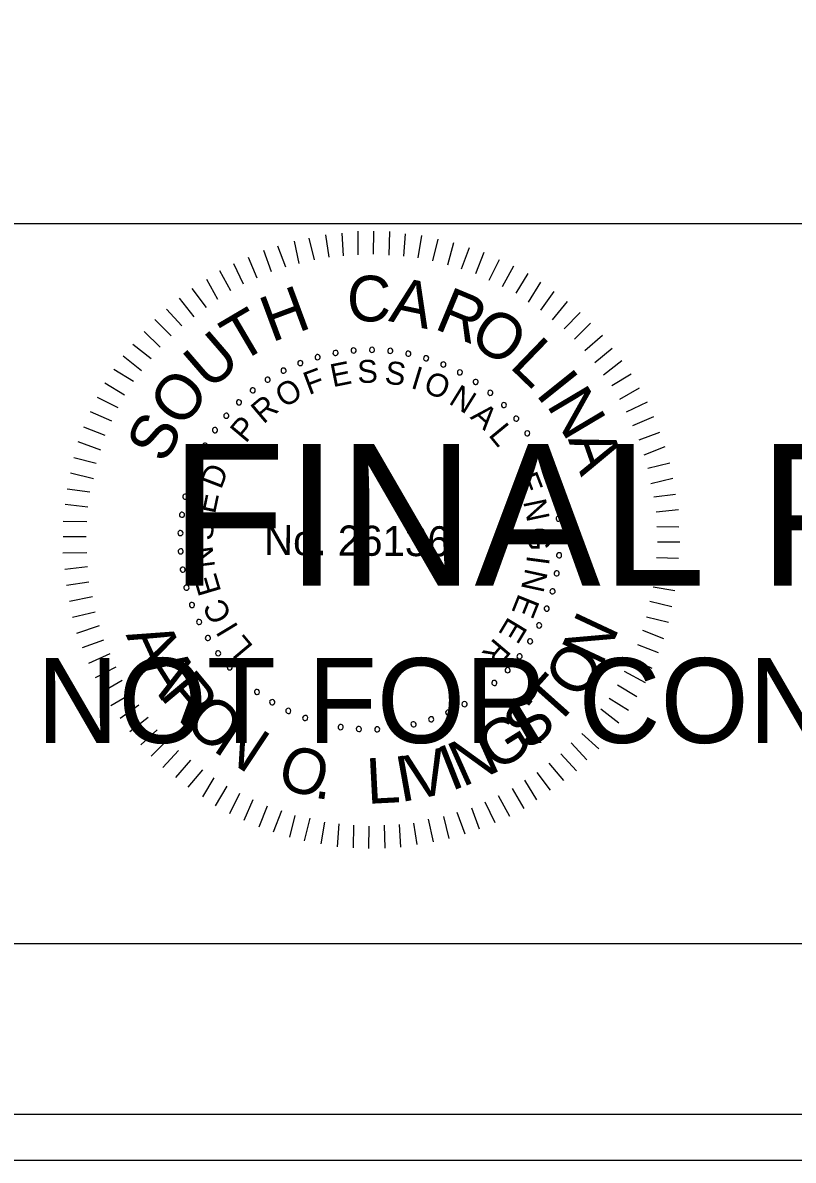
# Model space of a CAD drawing. Extents: x 967 to 1623, y 964 to 7064.
# Drawn here: x 1170.56 to 1189.3, y 2643.72 to 2671.36 of the extents above; entities that cross this region are included whole.
import ezdxf

# ---------------------------------------------------------------- set-up
doc = ezdxf.new("R2010")
doc.units = 0
for name, color, linetype in [('RD_SHT_Bndy', 7, 'Continuous'), ('RD_SHT_IplotShp', 7, 'Continuous'), ('RD_SHT_Misc1', 7, 'Continuous'), ('RD_SHT_Misc2', 7, 'Continuous'), ('RD_Sketch1', 7, 'Continuous')]:
    doc.layers.add(name, color=color, linetype=linetype)

msp = doc.modelspace()

# ---------------------------------------------------------------- linework, layer by layer
at = {"layer": 'RD_SHT_Bndy'}
for p, q in [((996.114, 2666.486), (1323.886, 2666.486)), ((1323.886, 2648.983), (996.114, 2648.983))]:
    msp.add_line(p, q, dxfattribs=at)
at = {"layer": 'RD_SHT_IplotShp'}
for points in [[(967.409, 2643.72), (1326.285, 2643.72), (1326.285, 2863.72), (967.409, 2863.72)], [(988.525, 2644.84), (1326.285, 2644.84), (1326.285, 2862.6), (988.525, 2862.6)]]:
    msp.add_lwpolyline(points, close=True, dxfattribs=at)
at = {"layer": 'RD_SHT_Misc1'}
for p, q in [((1178.01, 2665.663), (1177.93, 2666.209)), ((1178.364, 2665.699), (1178.33, 2666.244)), ((1178.717, 2665.719), (1178.722, 2666.295)), ((1179.093, 2665.739), (1179.098, 2666.292)), ((1179.469, 2665.713), (1179.489, 2666.288)), ((1179.829, 2665.687), (1179.872, 2666.231)), ((1180.174, 2665.646), (1180.271, 2666.19)), ((1176.964, 2665.419), (1176.769, 2665.935)), ((1177.287, 2665.508), (1177.169, 2666.054)), ((1177.657, 2665.597), (1177.53, 2666.128)), ((1180.535, 2665.573), (1180.662, 2666.102)), ((1180.902, 2665.478), (1181.045, 2666.022)), ((1181.231, 2665.384), (1181.428, 2665.896)), ((1176.264, 2665.156), (1176.053, 2665.657)), ((1176.61, 2665.306), (1176.423, 2665.83)), ((1181.584, 2665.265), (1181.78, 2665.786)), ((1181.905, 2665.109), (1182.154, 2665.606)), ((1175.624, 2664.846), (1175.352, 2665.332)), ((1175.933, 2665.005), (1175.699, 2665.506)), ((1182.226, 2664.953), (1182.506, 2665.45)), ((1175.308, 2664.634), (1175.036, 2665.12)), ((1182.562, 2664.789), (1182.85, 2665.27)), ((1182.86, 2664.572), (1183.163, 2665.053)), ((1175.03, 2664.445), (1174.681, 2664.9)), ((1183.158, 2664.378), (1183.484, 2664.828)), ((1174.729, 2664.217), (1174.372, 2664.665)), ((1183.447, 2664.145), (1183.811, 2664.587)), ((1174.435, 2663.997), (1174.062, 2664.399)), ((1183.729, 2663.92), (1184.116, 2664.316)), ((1174.172, 2663.753), (1173.776, 2664.148)), ((1183.98, 2663.672), (1184.368, 2664.061)), ((1173.909, 2663.479), (1173.52, 2663.858)), ((1184.232, 2663.394), (1184.657, 2663.767)), ((1173.684, 2663.197), (1173.242, 2663.546)), ((1184.475, 2663.108), (1184.892, 2663.45)), ((1173.451, 2662.9), (1173.009, 2663.256)), ((1184.687, 2662.807), (1185.128, 2663.156)), ((1173.257, 2662.64), (1172.776, 2662.936)), ((1184.885, 2662.544), (1185.355, 2662.832)), ((1173.039, 2662.312), (1172.559, 2662.6)), ((1185.081, 2662.213), (1185.56, 2662.493)), ((1172.883, 2662.006), (1172.379, 2662.256)), ((1185.24, 2661.904), (1185.756, 2662.145)), ((1172.727, 2661.677), (1172.215, 2661.904)), ((1185.399, 2661.573), (1185.907, 2661.791)), ((1172.571, 2661.333), (1172.051, 2661.53)), ((1172.461, 2660.974), (1171.91, 2661.178)), ((1185.549, 2661.226), (1186.057, 2661.414)), ((1185.669, 2660.865), (1186.185, 2661.06)), ((1172.351, 2660.652), (1171.807, 2660.787)), ((1185.759, 2660.541), (1186.297, 2660.667)), ((1172.286, 2660.276), (1171.727, 2660.419)), ((1185.832, 2660.165), (1186.371, 2660.298)), ((1172.191, 2659.955), (1171.647, 2660.029)), ((1185.906, 2659.842), (1186.436, 2659.906)), ((1172.15, 2659.587), (1171.598, 2659.653)), ((1185.964, 2659.473), (1186.51, 2659.53)), ((1172.124, 2659.234), (1171.548, 2659.239)), ((1185.977, 2659.12), (1186.514, 2659.115)), ((1172.105, 2658.866), (1171.545, 2658.871)), ((1185.997, 2658.751), (1186.542, 2658.747)), ((1172.118, 2658.482), (1171.542, 2658.471)), ((1172.138, 2658.136), (1171.585, 2658.072)), ((1185.971, 2658.368), (1186.508, 2658.348)), ((1185.952, 2658.022), (1186.497, 2657.949)), ((1172.173, 2657.768), (1171.627, 2657.688)), ((1185.888, 2657.655), (1186.417, 2657.566)), ((1172.262, 2657.414), (1171.701, 2657.296)), ((1185.808, 2657.302), (1186.345, 2657.175)), ((1172.321, 2657.037), (1171.774, 2656.911)), ((1185.729, 2656.926), (1186.265, 2656.792)), ((1172.425, 2656.707), (1171.871, 2656.519)), ((1185.634, 2656.597), (1186.146, 2656.401)), ((1172.53, 2656.36), (1172.007, 2656.173)), ((1185.508, 2656.253), (1186.013, 2656.057)), ((1172.681, 2656.029), (1172.165, 2655.788)), ((1185.352, 2655.924), (1185.857, 2655.675)), ((1172.831, 2655.705), (1172.323, 2655.441)), ((1172.982, 2655.374), (1172.497, 2655.094)), ((1185.188, 2655.603), (1185.7, 2655.33)), ((1185.024, 2655.274), (1185.498, 2654.987)), ((1173.194, 2655.042), (1172.709, 2654.762)), ((1184.822, 2654.946), (1185.288, 2654.658)), ((1173.384, 2654.78), (1172.936, 2654.453)), ((1184.62, 2654.687), (1185.055, 2654.353)), ((1173.612, 2654.478), (1173.164, 2654.129)), ((1184.403, 2654.389), (1184.814, 2654.033)), ((1173.832, 2654.177), (1173.437, 2653.812)), ((1184.155, 2654.092), (1184.574, 2653.72)), ((1174.091, 2653.945), (1173.689, 2653.541)), ((1183.899, 2653.864), (1184.28, 2653.454)), ((1174.35, 2653.674), (1173.97, 2653.263)), ((1174.64, 2653.442), (1174.275, 2653.022)), ((1183.644, 2653.597), (1184.024, 2653.18)), ((1174.937, 2653.209), (1174.58, 2652.782)), ((1183.065, 2653.141), (1183.384, 2652.709)), ((1183.358, 2653.37), (1183.715, 2652.944)), ((1175.212, 2653.014), (1174.932, 2652.549)), ((1182.764, 2652.952), (1183.059, 2652.482)), ((1175.525, 2652.812), (1175.245, 2652.331)), ((1175.83, 2652.633), (1175.588, 2652.136)), ((1182.463, 2652.755), (1182.743, 2652.269)), ((1176.159, 2652.477), (1175.94, 2651.98)), ((1176.503, 2652.321), (1176.307, 2651.816)), ((1181.8, 2652.431), (1182.041, 2651.93)), ((1182.124, 2652.581), (1182.396, 2652.08)), ((1176.855, 2652.211), (1176.651, 2651.69)), ((1177.177, 2652.1), (1177.05, 2651.572)), ((1177.545, 2652.036), (1177.409, 2651.484)), ((1180.791, 2652.07), (1180.926, 2651.54)), ((1181.122, 2652.175), (1181.31, 2651.652)), ((1181.476, 2652.28), (1181.664, 2651.771)), ((1177.897, 2651.933), (1177.808, 2651.412)), ((1178.25, 2651.892), (1178.207, 2651.34)), ((1178.603, 2651.866), (1178.598, 2651.313)), ((1178.978, 2651.84), (1178.974, 2651.295)), ((1179.355, 2651.86), (1179.365, 2651.307)), ((1179.715, 2651.88), (1179.749, 2651.327)), ((1180.061, 2651.915), (1180.149, 2651.393)), ((1180.423, 2652.012), (1180.541, 2651.458))]:
    msp.add_line(p, q, dxfattribs=at)
for centre, start, end in [((1178.168, 2663.337), 10.6038, 190.6038), ((1178.609, 2663.397), 5.0653, 185.0653), ((1178.609, 2663.397), 185.0653, 5.0653), ((1179.055, 2663.414), 359.5268, 179.5268), ((1179.055, 2663.414), 179.5268, 359.5268), ((1179.5, 2663.388), 353.9884, 173.9884), ((1179.5, 2663.388), 173.9884, 353.9884), ((1179.94, 2663.319), 348.4499, 168.4499), ((1177.312, 2663.091), 21.6807, 201.6807), ((1177.312, 2663.091), 201.6807, 21.6807), ((1177.734, 2663.235), 16.1422, 196.1422), ((1177.734, 2663.235), 196.1422, 16.1422), ((1178.168, 2663.337), 190.6038, 10.6038), ((1179.94, 2663.319), 168.4499, 348.4499), ((1180.372, 2663.208), 162.9114, 342.9114), ((1180.372, 2663.208), 342.9114, 162.9114), ((1180.79, 2663.056), 337.373, 157.373), ((1176.906, 2662.908), 27.2191, 207.2191), ((1176.906, 2662.908), 207.2191, 27.2191), ((1180.79, 2663.056), 157.373, 337.373), ((1181.193, 2662.864), 151.8345, 331.8345), ((1181.193, 2662.864), 331.8345, 151.8345), ((1176.52, 2662.686), 32.7576, 212.7576), ((1176.52, 2662.686), 212.7576, 32.7576), ((1181.574, 2662.634), 146.2961, 326.2961), ((1181.574, 2662.634), 326.2961, 146.2961), ((1176.156, 2662.428), 38.2961, 218.2961), ((1176.156, 2662.428), 218.2961, 38.2961), ((1181.932, 2662.368), 140.7576, 320.7576), ((1181.932, 2662.368), 320.7576, 140.7576), ((1175.82, 2662.135), 43.8345, 223.8345), ((1175.82, 2662.135), 223.8345, 43.8345), ((1182.263, 2662.069), 135.2191, 315.2191), ((1182.263, 2662.069), 315.2191, 135.2191), ((1175.513, 2661.812), 49.373, 229.373), ((1175.513, 2661.812), 229.373, 49.373), ((1182.563, 2661.74), 129.6807, 309.6807), ((1182.563, 2661.74), 309.6807, 129.6807), ((1175.239, 2661.461), 54.9114, 234.9114), ((1175.239, 2661.461), 234.9114, 54.9114), ((1182.83, 2661.383), 124.1422, 304.1422), ((1182.83, 2661.383), 304.1422, 124.1422), ((1175, 2661.085), 60.4499, 240.4499), ((1175, 2661.085), 240.4499, 60.4499), ((1183.061, 2661.002), 118.6038, 298.6038), ((1183.061, 2661.002), 298.6038, 118.6038), ((1174.798, 2660.687), 65.9884, 245.9884), ((1174.798, 2660.687), 245.9884, 65.9884), ((1183.255, 2660.601), 113.0653, 293.0653), ((1183.255, 2660.601), 293.0653, 113.0653), ((1174.636, 2660.272), 71.5268, 251.5268), ((1174.636, 2660.272), 251.5268, 71.5268), ((1183.408, 2660.182), 107.5268, 287.5268), ((1183.408, 2660.182), 287.5268, 107.5268), ((1174.514, 2659.843), 77.0653, 257.0653), ((1174.514, 2659.843), 257.0653, 77.0653), ((1183.521, 2659.751), 101.9884, 281.9884), ((1183.521, 2659.751), 281.9884, 101.9884), ((1174.435, 2659.405), 82.6038, 262.6038), ((1174.435, 2659.405), 262.6038, 82.6038), ((1183.592, 2659.311), 96.4499, 276.4499), ((1183.592, 2659.311), 276.4499, 96.4499), ((1174.398, 2658.961), 88.1422, 268.1422), ((1174.398, 2658.961), 268.1422, 88.1422), ((1183.619, 2658.866), 90.9114, 270.9114), ((1183.619, 2658.866), 270.9114, 90.9114), ((1174.404, 2658.515), 93.6807, 273.6807), ((1174.404, 2658.515), 273.6807, 93.6807), ((1183.604, 2658.421), 85.373, 265.373), ((1183.604, 2658.421), 265.373, 85.373), ((1174.453, 2658.072), 99.2191, 279.2191), ((1174.453, 2658.072), 279.2191, 99.2191), ((1183.546, 2657.979), 79.8345, 259.8345), ((1183.546, 2657.979), 259.8345, 79.8345), ((1174.545, 2657.636), 104.7576, 284.7576), ((1174.545, 2657.636), 284.7576, 104.7576), ((1183.445, 2657.545), 74.2961, 254.2961), ((1183.445, 2657.545), 254.2961, 74.2961), ((1174.678, 2657.211), 110.2961, 290.2961), ((1174.678, 2657.211), 290.2961, 110.2961), ((1183.303, 2657.122), 68.7576, 248.7576), ((1183.303, 2657.122), 248.7576, 68.7576), ((1174.852, 2656.8), 115.8345, 295.8345), ((1174.852, 2656.8), 295.8345, 115.8345), ((1183.121, 2656.716), 63.2191, 243.2191), ((1183.121, 2656.716), 243.2191, 63.2191), ((1175.065, 2656.409), 121.373, 301.373), ((1175.065, 2656.409), 301.373, 121.373), ((1182.9, 2656.328), 57.6807, 237.6807), ((1182.9, 2656.328), 237.6807, 57.6807), ((1175.314, 2656.039), 126.9114, 306.9114), ((1175.314, 2656.039), 306.9114, 126.9114), ((1182.643, 2655.964), 52.1422, 232.1422), ((1182.643, 2655.964), 232.1422, 52.1422), ((1175.598, 2655.696), 132.4499, 312.4499), ((1175.598, 2655.696), 312.4499, 132.4499), ((1182.353, 2655.627), 46.6038, 226.6038), ((1182.353, 2655.627), 226.6038, 46.6038), ((1175.914, 2655.381), 137.9884, 317.9884), ((1175.914, 2655.381), 317.9884, 137.9884), ((1182.03, 2655.319), 41.0653, 221.0653), ((1182.03, 2655.319), 221.0653, 41.0653), ((1176.258, 2655.099), 143.5268, 323.5268), ((1176.258, 2655.099), 323.5268, 143.5268), ((1181.68, 2655.043), 35.5268, 215.5268), ((1181.68, 2655.043), 215.5268, 35.5268), ((1176.629, 2654.851), 149.0653, 329.0653), ((1176.629, 2654.851), 329.0653, 149.0653), ((1181.305, 2654.803), 29.9884, 209.9884), ((1181.305, 2654.803), 209.9884, 29.9884), ((1177.021, 2654.639), 154.6038, 334.6038), ((1177.021, 2654.639), 334.6038, 154.6038), ((1177.432, 2654.467), 340.1422, 160.1422), ((1180.908, 2654.6), 24.4499, 204.4499), ((1180.908, 2654.6), 204.4499, 24.4499), ((1177.432, 2654.467), 160.1422, 340.1422), ((1177.858, 2654.335), 165.6807, 345.6807), ((1177.858, 2654.335), 345.6807, 165.6807), ((1178.294, 2654.245), 351.2191, 171.2191), ((1178.294, 2654.245), 171.2191, 351.2191), ((1178.737, 2654.198), 356.7576, 176.7576), ((1179.183, 2654.193), 2.2961, 182.2961), ((1179.627, 2654.232), 7.8345, 187.8345), ((1180.065, 2654.313), 13.373, 193.373), ((1180.065, 2654.313), 193.373, 13.373), ((1180.494, 2654.436), 18.9114, 198.9114), ((1180.494, 2654.436), 198.9114, 18.9114), ((1178.737, 2654.198), 176.7576, 356.7576), ((1179.183, 2654.193), 182.2961, 2.2961), ((1179.627, 2654.232), 187.8345, 7.8345)]:
    msp.add_arc(centre, 0.0627, start, end, dxfattribs=at)
at = {"layer": 'RD_Sketch1'}
msp.add_lwpolyline([(967.409, 2643.72), (1326.285, 2643.72), (1326.285, 2863.72), (967.409, 2863.72)], close=True, dxfattribs=at)

# ---------------------------------------------------------------- texts
at = {"layer": 'RD_SHT_Misc1'}
for s, height, rotation, p in [('C', 1.11, 359.5482, (1178.442, 2664.108)), ('A', 1.11, 348.1981, (1179.439, 2664.115)), ('H', 1.11, 20.3637, (1176.614, 2663.587)), ('R', 1.11, 337.4344, (1180.541, 2663.937)), ('T', 1.11, 30.4992, (1175.828, 2663.072)), ('O', 1.108, 326.5869, (1181.366, 2663.609)), ('U', 1.11, 40.8022, (1175.102, 2662.403)), ('L', 1.11, 315.9488, (1182.373, 2663.003)), ('E', 0.557, 11.4103, (1178.103, 2662.503)), ('S', 0.557, 2.208, (1178.709, 2662.601)), ('S', 0.557, 352.6608, (1179.346, 2662.599)), ('O', 1.11, 52.0267, (1174.435, 2661.474)), ('F', 0.557, 20.6127, (1177.52, 2662.309)), ('I', 0.557, 343.1136, (1179.975, 2662.491)), ('O', 0.557, 338.4392, (1180.274, 2662.401)), ('I', 1.11, 308.6613, (1183.011, 2662.338)), ('O', 0.557, 30.8477, (1176.917, 2661.987)), ('N', 0.557, 328.2042, (1180.896, 2662.12)), ('R', 0.557, 40.3949, (1176.415, 2661.594)), ('N', 1.11, 300.7037, (1183.285, 2662.075)), ('A', 0.557, 318.657, (1181.424, 2661.762)), ('S', 1.108, 63.2511, (1174.029, 2660.619)), ('P', 0.557, 49.9421, (1175.985, 2661.124)), ('L', 0.557, 309.4546, (1181.869, 2661.339)), ('A', 1.11, 289.4792, (1183.814, 2661.243)), ('D', 0.557, 69.0364, (1175.386, 2660.003)), ('E', 0.557, 291.049, (1182.53, 2660.307)), ('E', 0.557, 78.2388, (1175.238, 2659.407)), ('N', 0.557, 281.8466, (1182.728, 2659.726)), ('S', 0.557, 87.786, (1175.187, 2658.772)), ('No. 26136', 0.7311, 359.5268, (1176.429, 2658.43)), ('G', 0.557, 272.2995, (1182.833, 2659.097)), ('N', 0.557, 97.3332, (1175.242, 2658.137)), ('I', 0.557, 262.4084, (1182.83, 2658.437)), ('E', 0.557, 106.5355, (1175.394, 2657.541)), ('N', 0.557, 257.7339, (1182.789, 2658.127)), ('C', 0.557, 116.4266, (1175.661, 2656.938)), ('E', 0.557, 248.1867, (1182.628, 2657.511)), ('N', 1.105, 64.8922, (1184.632, 2655.684)), ('I', 0.557, 121.1011, (1175.823, 2656.67)), ('E', 0.557, 238.9844, (1182.378, 2656.949)), ('A', 1.105, 294.7297, (1173.062, 2656.486)), ('L', 0.557, 129.9595, (1176.187, 2656.204)), ('R', 0.557, 229.782, (1182.041, 2656.435)), ('O', 1.105, 56.2059, (1184.102, 2654.874)), ('A', 1.105, 302.2892, (1173.414, 2655.72)), ('R', 1.105, 309.8487, (1173.865, 2655.007)), ('T', 1.105, 48.2685, (1183.515, 2654.211)), ('O', 1.105, 317.7861, (1174.434, 2654.33)), ('S', 1.105, 40.3311, (1182.842, 2653.636)), ('N', 1.105, 326.4725, (1175.158, 2653.686)), ('G', 1.105, 32.0198, (1182.059, 2653.14)), ('N', 1.105, 24.0824, (1181.252, 2652.776)), ('O', 1.105, 342.3472, (1176.697, 2652.82)), ('V', 1.105, 12.7741, (1180.033, 2652.457)), ('I', 1.105, 21.4605, (1180.976, 2652.681)), ('L', 1.105, 2.9677, (1178.943, 2652.379)), ('I', 1.105, 10.1523, (1179.743, 2652.418)), ('.', 1.105, 351.0336, (1177.623, 2652.536))]:
    msp.add_text(s, height=height, rotation=rotation, dxfattribs=at).set_placement(p)
at = {"layer": 'RD_SHT_Misc2'}
for s, height, p in [('FINAL PLANS', 3.4375, (1174.145, 2657.685)), ('NOT FOR CONSTRUCTION', 2.0625, (1170.901, 2653.86))]:
    msp.add_text(s, height=height, dxfattribs=at).set_placement(p)

doc.saveas('drawing.dxf')
